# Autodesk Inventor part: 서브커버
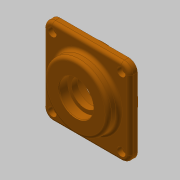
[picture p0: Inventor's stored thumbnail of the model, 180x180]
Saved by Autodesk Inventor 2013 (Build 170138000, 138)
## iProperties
Created: 2018-09
Part Number: 서브커버
Material: 알루미늄 6061
Document SubType Name: Modeling
Designer: mduedu
Density: 1 g/cm^3
Author: mduedu
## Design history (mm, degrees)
sketch "스케치1"
  geometry: L1 (-40, -40)-(40, -40); L2 (40, -40)-(40, 40); L3 (40, 40)-(-40, 40); L4 (-40, 40)-(-40, -40); L5 (-40, -40)-(40, 40); L6 (40, -40)-(-40, 40); 1 further point
  constraints: 12 end point, 2 midpoint, 2 parallel, 1 horizontal, 1 perpendicular
  dimensions: "d0" = 80 distance of L3.end L2.end; "d1" = 80 distance of L2.end L1.end
extrude "돌출1" new body sketch "스케치1" distance "d2" = 7; taper "d3" = 0 deg
sketch "스케치2"
  geometry: C1 r 30 at (0, 0); 1 further point
  constraints: 1 centre point, 1 coincident
  dimensions: "d4" = 60 diameter of C1
extrude "돌출2" join sketch "스케치2" distance "d5" = 10; taper "d6" = 0 deg
sketch "스케치3"
  geometry: C1 r 32.5 at (0, 0); 1 further point
  constraints: 1 centre point, 1 coincident
  dimensions: "d7" = 65 diameter of C1
extrude "돌출3" join sketch "스케치3" distance "d8" = 9; taper "d9" = 0 deg
sketch "스케치4"
  geometry: L1 (-32.5, -9)-(32.5, -9) reference; L2 (30, 17)-(-30, 17) reference; L3 (0, 17)-(0, -9); L4 (0, -9)-(20, -9); L5 (20, -9)-(20, 3); L6 (20, 3)-(0, 3); L7 (0, 3)-(0, -9); L8 (0, 3)-(12.5, 3); L9 (12.5, 3)-(12.5, 8.7); L10 (12.5, 8.7)-(0, 8.7); L11 (0, 8.7)-(0, 3); L12 (0, 8.7)-(16, 8.7); L13 (16, 8.7)-(16, 17); L14 (16, 17)-(0, 17); L15 (0, 17)-(0, 8.7); 1 further point
  constraints: 26 end point, 6 parallel, 3 horizontal, 3 perpendicular, 2 midpoint, 1 point on line
  dimensions: "d10" = 12 distance of L4.end L5.end; "d12" = 8.3 distance of L12.end L13.end; "d13" = 32 diameter of L13 L3; "d14" = 25 diameter of L9 L3; "d15" = 40 diameter of L5 L3
revolve "회전1" sketch "스케치4" stored, may be unused: angle "d16" = 90 deg
fillet "모깎기1" dims "d17" = 8
fillet "모깎기2" dims "d18" = 3
fillet "모깎기3" dims "d19" = 3
chamfer "모따기1" distance "d20" = 0.8; stored, may be unused: second distance "d21" = 2, angle "d22" = 30 deg
chamfer "모따기2" distance "d23" = 1; stored, may be unused: second distance "d24" = 2, angle "d25" = 30 deg
fillet "모깎기4" dims "d26" = 0.3
sketch "스케치5"
  geometry: A1 r 8 centre (-32, 32) between (-32, 40) and (-40, 32) reference; A2 r 8 centre (-32, -32) between (-40, -32) and (-32, -40) reference; A3 r 8 centre (32, -32) between (32, -40) and (40, -32) reference; A4 r 8 centre (32, 32) between (40, 32) and (32, 40) reference; 5 further points
  constraints: 4 coincident
hole "구멍1" sketch "스케치5" at (-32, 32), (32, 32), (32, -32), (-32, -32) diameter "d27" = 4.5; stored, may be unused: countersink angle "d31" = 90 deg, drill point angle "d33" = 118 deg; dims "d28" = 6, "d29" = 8, "d30" = 4.4, "d32" = 8
node "솔리드1"
